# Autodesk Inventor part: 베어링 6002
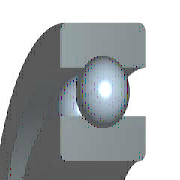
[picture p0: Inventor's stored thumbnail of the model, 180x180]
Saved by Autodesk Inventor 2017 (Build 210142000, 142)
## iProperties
Created: 2012-02
Part Number: 베어링 6002
Material: 강철, 연강
Description: 깊은 그루브 볼 베어링
Document SubType Name: Modeling
Standard: KS B 2023
Designer: mduedu
Standards Organization: KS
Language: ko-KR
Size Designation: 6002 - 15 x 32 x 9
Categories: <MemberInstance><Categories><Category DisplayName="샤프트 부품" InternalName="7f7aeb1f-a693-4053-b835-cee3144e0d98" Mnemonic="SHFT"><Category DisplayName="베어링" Inter
Density: 7.86 g/cm^3
Mass: 29.8124 g
Surface Area: 39.9079 cm^2
Volume: 3.79293 cm^3
Appearance: 분홍색
IsCustomPart: 1
Author: mduedu
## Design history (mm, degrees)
sketch "스케치" dims "d0" = 4.42 (= -0.26 x WD + 0.26 x BD)
  geometry: L1 (2.29, 11.75)-(6.71, 11.75); L2 (4.5, 11.75)-(4.5, 9.54); L3 (4.5, 11.75)-(4.5, 13.96); L4 (2.858, 10.271)-(0, 10.271); L5 (0, 7.5)-(9, 7.5); L6 (2.858, 13.229)-(0, 13.229); L7 (0, 16)-(9, 16); L8 (9, 7.5)-(9, 10.271); L9 (6.142, 10.271)-(9, 10.271); L10 (6.142, 13.229)-(9, 13.229); L11 (9, 16)-(9, 13.229); L12 (-1.4, 0)-(8.4, 0) reference; L13 (0, -0.3)-(0, 5.3) reference
  constraints: 22 end point, 4 point on line, 2 collinear, 2 perpendicular, 2 symmetric about line, 1 midpoint, 1 parallel, 14 other
  dimensions: "d9" = 15 diameter of L5 L12 (= WD); "d11" = 32 diameter of L7 L12 (= BD); "d12" = 9 distance between parallel lines of L8 L13 (= KB); "d13" = 20.542 diameter of L9 L12 (= 0.326 x BD + 0.674 x WD)
revolve "본체" stored, may be unused: angle "d6" = 90 deg
revolve "볼" stored, may be unused: angle "d7" = 90 deg
pattern_circular "IDS_ARRAYBALL[SIMPL:T]" dims angle "d3" = 360 deg
body "Solid1"
fillet "모깎기1" dims "d1" = 0.3 (= KRS)
other parameters: "WD" = 15 [user parameter; used in 5 equation terms], "BD" = 32 [user parameter; used in 5 equation terms], "KB" = 9 [user parameter; used in 1 equation term], "KRS" = 0.3 [user parameter; used in 1 equation term], "d4" = 0, "d5" = 0, "d8" = 0, "d14" = 0, "d15" = 0, "BBA" = 0 [user parameter], "BC0" = 2850000 [user parameter], "BC" = 5590000 [user parameter], "BR" = 16 (= 0.5 x BD) [user parameter], "WR" = 7.5 (= 0.5 x WD) [user parameter]
